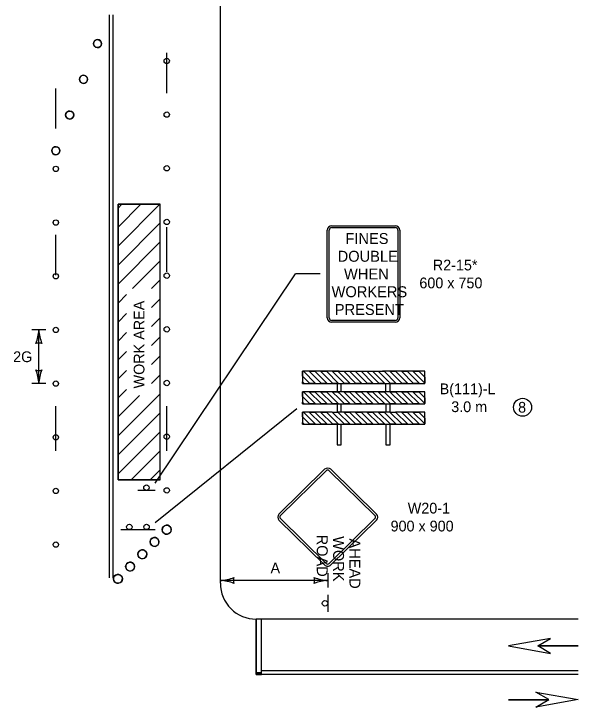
# Model space of a CAD drawing. Extents: x 49991.4 to 50021, y 49987.6 to 50011.4.
# Drawn here: x 50009.955 to 50013.109, y 49992.332 to 49996.207 of the extents above; entities that cross this region are included whole.
import ezdxf

# ---------------------------------------------------------------- set-up
doc = ezdxf.new("R2010")
doc.units = 0
for name, color, linetype in [('Level 1', 7, 'Continuous'), ('Level 2', 7, 'Continuous'), ('Level 3', 7, 'Continuous')]:
    doc.layers.add(name, color=color, linetype=linetype)

msp = doc.modelspace()

# ---------------------------------------------------------------- linework, layer by layer
at = {"layer": 'Level 1'}
for p, q in [((50011.109, 49995.0313), (50011.109, 49998.8719)), ((50010.489, 49995.4153), (50010.489, 49996.2021)), ((50010.509, 49995.4153), (50010.509, 49996.2021)), ((50010.8092, 49995.764), (50010.8092, 49995.988)), ((50010.1892, 49995.5651), (50010.1892, 49995.7891)), ((50010.489, 49995.3665), (50010.489, 49995.6141)), ((50010.509, 49995.3141), (50010.509, 49995.6141)), ((50010.489, 49995.0665), (50010.489, 49995.3665)), ((50010.509, 49995.0141), (50010.509, 49995.3141)), ((50010.5369, 49993.6029), (50010.5369, 49995.1428)), ((50010.5369, 49995.1428), (50010.7724, 49995.1428)), ((50010.5369, 49995.1207), (50010.559, 49995.1428)), ((50010.5369, 49995.0146), (50010.665, 49995.1428)), ((50010.5369, 49994.9086), (50010.7711, 49995.1428)), ((50010.7724, 49993.6029), (50010.7724, 49995.1428)), ((50010.489, 49994.7665), (50010.489, 49995.0665)), ((50010.5369, 49994.8025), (50010.7724, 49995.038)), ((50011.109, 49993.024), (50011.109, 49995.0313)), ((50010.509, 49994.7141), (50010.509, 49995.0141)), ((50010.8092, 49994.764), (50010.8092, 49995.014)), ((50011.7068, 49994.5081), (50011.7068, 49994.9975)), ((50011.7173, 49994.5081), (50011.7173, 49994.9975)), ((50011.7321, 49995.0228), (50012.0865, 49995.0228)), ((50011.7321, 49995.0123), (50012.0865, 49995.0123)), ((50011.9093, 49995.0228), (50011.9093, 49995.0228)), ((50012.1013, 49994.9975), (50012.1013, 49994.5081)), ((50012.1118, 49994.9975), (50012.1118, 49994.5081)), ((50010.1892, 49994.7461), (50010.1892, 49994.9711)), ((50010.5369, 49994.6964), (50010.7724, 49994.9319)), ((50010.6178, 49994.6712), (50010.7724, 49994.8259)), ((50010.489, 49994.4141), (50010.489, 49994.7665)), ((50010.7238, 49994.6712), (50010.7724, 49994.7198)), ((50010.509, 49994.4141), (50010.509, 49994.7141)), ((50010.5369, 49994.5904), (50010.5846, 49994.6381)), ((50010.7246, 49994.566), (50010.7724, 49994.6137)), ((50010.5369, 49994.4843), (50010.5846, 49994.5321)), ((50010.7246, 49994.4599), (50010.7724, 49994.5077)), ((50012.0865, 49994.4933), (50011.7321, 49994.4933)), ((50012.0865, 49994.4827), (50011.7321, 49994.4827)), ((50010.489, 49994.1141), (50010.489, 49994.4141)), ((50010.509, 49994.1141), (50010.509, 49994.4141)), ((50010.5369, 49994.3783), (50010.5846, 49994.426)), ((50010.7246, 49994.3539), (50010.7724, 49994.4016)), ((50010.5369, 49994.2722), (50010.5846, 49994.3199)), ((50010.7246, 49994.2478), (50010.7724, 49994.2956)), ((50010.5369, 49994.1661), (50010.5846, 49994.2139)), ((50010.7246, 49994.1417), (50010.7724, 49994.1895)), ((50011.6091, 49994.1407), (50011.5673, 49994.1824)), ((50011.6091, 49994.1407), (50011.5673, 49994.1824)), ((50011.6413, 49994.1407), (50011.5729, 49994.2091)), ((50011.5729, 49994.2091), (50011.6413, 49994.1407)), ((50011.6736, 49994.1407), (50011.6052, 49994.2091)), ((50011.6736, 49994.1407), (50011.6052, 49994.2091)), ((50011.7058, 49994.1407), (50011.6374, 49994.2091)), ((50011.6374, 49994.2091), (50011.7058, 49994.1407)), ((50011.738, 49994.1407), (50011.6696, 49994.2091)), ((50011.738, 49994.1407), (50011.6696, 49994.2091)), ((50011.7703, 49994.1407), (50011.7019, 49994.2091)), ((50011.7019, 49994.2091), (50011.7703, 49994.1407)), ((50011.8025, 49994.1407), (50011.7341, 49994.2091)), ((50011.8347, 49994.1407), (50011.7663, 49994.2091)), ((50011.7663, 49994.2091), (50011.8062, 49994.2091)), ((50011.7868, 49994.2091), (50012.0318, 49994.2091)), ((50011.8669, 49994.1407), (50011.7985, 49994.2091)), ((50011.8991, 49994.1407), (50011.8308, 49994.2091)), ((50011.9313, 49994.1407), (50011.863, 49994.2091)), ((50011.9636, 49994.1407), (50011.8952, 49994.2091)), ((50011.9958, 49994.1407), (50011.9274, 49994.2091)), ((50012.028, 49994.1407), (50011.9596, 49994.2091)), ((50012.0604, 49994.1407), (50011.992, 49994.2091)), ((50012.0461, 49994.2091), (50012.0148, 49994.2091)), ((50012.0926, 49994.1407), (50012.0242, 49994.2091)), ((50012.1249, 49994.1407), (50012.0565, 49994.2091)), ((50012.1249, 49994.1407), (50012.0565, 49994.2091)), ((50012.1571, 49994.1407), (50012.0887, 49994.2091)), ((50012.0887, 49994.2091), (50012.1571, 49994.1407)), ((50012.1894, 49994.1407), (50012.121, 49994.2091)), ((50012.1894, 49994.1407), (50012.121, 49994.2091)), ((50012.2216, 49994.1407), (50012.1532, 49994.2091)), ((50012.1532, 49994.2091), (50012.2216, 49994.1407)), ((50012.2513, 49994.1432), (50012.1854, 49994.2091)), ((50012.2513, 49994.1432), (50012.1854, 49994.2091)), ((50012.2513, 49994.1755), (50012.2177, 49994.2091)), ((50012.2177, 49994.2091), (50012.2513, 49994.1755)), ((50011.5768, 49994.1407), (50011.5673, 49994.1502)), ((50011.5673, 49994.1502), (50011.5768, 49994.1407)), ((50011.7839, 49994.0951), (50011.7839, 49994.1407)), ((50012.0347, 49994.0951), (50012.0347, 49994.1407)), ((50010.489, 49993.8665), (50010.489, 49994.1141)), ((50010.509, 49993.8141), (50010.509, 49994.1141)), ((50010.5369, 49994.0601), (50010.5846, 49994.1078)), ((50010.5369, 49993.8479), (50010.7724, 49994.0834)), ((50010.5369, 49993.954), (50010.6573, 49994.0744)), ((50011.6091, 49994.0267), (50011.5673, 49994.0685)), ((50011.6091, 49994.0267), (50011.5673, 49994.0685)), ((50011.6413, 49994.0267), (50011.5729, 49994.0951)), ((50011.5729, 49994.0951), (50011.6413, 49994.0267)), ((50011.6736, 49994.0267), (50011.6052, 49994.0951)), ((50011.6736, 49994.0267), (50011.6052, 49994.0951)), ((50011.7058, 49994.0267), (50011.6374, 49994.0951)), ((50011.6374, 49994.0951), (50011.7058, 49994.0267)), ((50011.738, 49994.0267), (50011.6696, 49994.0951)), ((50011.738, 49994.0267), (50011.6696, 49994.0951)), ((50011.7703, 49994.0267), (50011.7019, 49994.0951)), ((50011.7019, 49994.0951), (50011.7703, 49994.0267)), ((50011.7725, 49994.0568), (50011.7341, 49994.0951)), ((50011.7725, 49994.089), (50011.7663, 49994.0951)), ((50011.8347, 49994.0267), (50011.7725, 49994.089)), ((50011.867, 49994.0267), (50011.7986, 49994.0951)), ((50011.8992, 49994.0267), (50011.8308, 49994.0951)), ((50011.9315, 49994.0267), (50011.8631, 49994.0951)), ((50011.9637, 49994.0267), (50011.8953, 49994.0951)), ((50011.9959, 49994.0267), (50011.9275, 49994.0951)), ((50012.0282, 49994.0267), (50011.9598, 49994.0951)), ((50012.0604, 49994.0267), (50011.992, 49994.0951)), ((50012.0926, 49994.0267), (50012.0242, 49994.0951)), ((50012.1249, 49994.0267), (50012.0565, 49994.0951)), ((50012.1249, 49994.0267), (50012.0565, 49994.0951)), ((50012.1571, 49994.0267), (50012.0887, 49994.0951)), ((50012.0887, 49994.0951), (50012.1571, 49994.0267)), ((50012.1894, 49994.0267), (50012.121, 49994.0951)), ((50012.1894, 49994.0267), (50012.121, 49994.0951)), ((50012.2216, 49994.0267), (50012.1532, 49994.0951)), ((50012.1532, 49994.0951), (50012.2216, 49994.0267)), ((50012.2513, 49994.0293), (50012.1854, 49994.0951)), ((50012.2513, 49994.0293), (50012.1854, 49994.0951)), ((50012.2513, 49994.0615), (50012.2177, 49994.0951)), ((50012.2177, 49994.0951), (50012.2513, 49994.0615)), ((50011.5768, 49994.0267), (50011.5673, 49994.0363)), ((50011.5673, 49994.0363), (50011.5768, 49994.0267)), ((50011.8025, 49994.0267), (50011.7725, 49994.0568)), ((50010.1892, 49993.764), (50010.1892, 49994.014)), ((50010.8092, 49993.764), (50010.8092, 49994.014)), ((50010.5369, 49993.7419), (50010.7724, 49993.9774)), ((50011.6091, 49993.9128), (50011.5673, 49993.9545)), ((50011.6091, 49993.9128), (50011.5673, 49993.9545)), ((50011.6413, 49993.9128), (50011.5729, 49993.9812)), ((50011.5729, 49993.9812), (50011.6413, 49993.9128)), ((50011.6736, 49993.9128), (50011.6052, 49993.9812)), ((50011.6736, 49993.9128), (50011.6052, 49993.9812)), ((50011.7058, 49993.9128), (50011.6374, 49993.9812)), ((50011.6374, 49993.9812), (50011.7058, 49993.9128)), ((50011.738, 49993.9128), (50011.6696, 49993.9812)), ((50011.738, 49993.9128), (50011.6696, 49993.9812)), ((50011.7703, 49993.9128), (50011.7019, 49993.9812)), ((50011.7019, 49993.9812), (50011.7703, 49993.9128)), ((50011.8025, 49993.9128), (50011.7341, 49993.9812)), ((50011.8025, 49993.9128), (50011.7341, 49993.9812)), ((50011.8347, 49993.9128), (50011.7663, 49993.9812)), ((50011.7663, 49993.9812), (50011.8347, 49993.9128)), ((50011.867, 49993.9128), (50011.7986, 49993.9812)), ((50011.867, 49993.9128), (50011.7986, 49993.9812)), ((50011.8992, 49993.9128), (50011.8308, 49993.9812)), ((50011.8308, 49993.9812), (50011.8992, 49993.9128)), ((50011.9315, 49993.9128), (50011.8631, 49993.9812)), ((50011.9315, 49993.9128), (50011.8631, 49993.9812)), ((50011.9637, 49993.9128), (50011.8953, 49993.9812)), ((50011.8953, 49993.9812), (50011.9637, 49993.9128)), ((50011.9959, 49993.9128), (50011.9275, 49993.9812)), ((50011.9959, 49993.9128), (50011.9275, 49993.9812)), ((50012.0282, 49993.9128), (50011.9598, 49993.9812)), ((50011.9598, 49993.9812), (50012.0282, 49993.9128)), ((50012.0604, 49993.9128), (50011.992, 49993.9812)), ((50012.0604, 49993.9128), (50011.992, 49993.9812)), ((50012.0926, 49993.9128), (50012.0242, 49993.9812)), ((50012.0242, 49993.9812), (50012.0926, 49993.9128)), ((50012.1249, 49993.9128), (50012.0565, 49993.9812)), ((50012.1249, 49993.9128), (50012.0565, 49993.9812)), ((50012.1571, 49993.9128), (50012.0887, 49993.9812)), ((50012.0887, 49993.9812), (50012.1571, 49993.9128)), ((50012.1894, 49993.9128), (50012.121, 49993.9812)), ((50012.1894, 49993.9128), (50012.121, 49993.9812)), ((50012.2216, 49993.9128), (50012.1532, 49993.9812)), ((50012.1532, 49993.9812), (50012.2216, 49993.9128)), ((50012.2513, 49993.9153), (50012.1854, 49993.9812)), ((50012.2513, 49993.9153), (50012.1854, 49993.9812)), ((50012.2513, 49993.9476), (50012.2177, 49993.9812)), ((50012.2177, 49993.9812), (50012.2513, 49993.9476)), ((50011.5768, 49993.9128), (50011.5673, 49993.9223)), ((50011.5673, 49993.9223), (50011.5768, 49993.9128)), ((50010.489, 49993.5782), (50010.489, 49993.8665)), ((50010.5369, 49993.6358), (50010.7724, 49993.8713)), ((50010.509, 49993.5024), (50010.509, 49993.8141)), ((50010.61, 49993.6029), (50010.7724, 49993.7652)), ((50010.7161, 49993.6029), (50010.7724, 49993.6592)), ((50011.4366, 49993.4113), (50011.6919, 49993.6613)), ((50011.4448, 49993.4029), (50011.7001, 49993.653)), ((50011.7179, 49993.653), (50011.9731, 49993.4029)), ((50011.7261, 49993.6613), (50011.9813, 49993.4113)), ((50010.7724, 49993.6029), (50010.5369, 49993.6029)), ((50010.489, 49993.2782), (50010.489, 49993.5782)), ((50010.509, 49993.5153), (50010.509, 49993.5174)), ((50010.7441, 49993.5435), (50010.6481, 49993.5435)), ((50010.509, 49993.2782), (50010.509, 49993.5024)), ((50011.6919, 49993.127), (50011.4366, 49993.377)), ((50011.7001, 49993.1353), (50011.4448, 49993.3854)), ((50011.9731, 49993.3854), (50011.7179, 49993.1353)), ((50011.9813, 49993.377), (50011.7261, 49993.127)), ((50010.5521, 49993.3239), (50010.6481, 49993.3239)), ((50010.6481, 49993.3239), (50010.7441, 49993.3239)), ((50010.489, 49993.054), (50010.489, 49993.2782)), ((50010.509, 49993.054), (50010.509, 49993.2782)), ((50010.509, 49993.2153), (50010.509, 49993.2174)), ((50010.5463, 49993.024), (50010.5463, 49993.0261)), ((50011.709, 49992.96), (50011.709, 49992.864)), ((50013.109, 49992.824), (50011.309, 49992.824)), ((50011.309, 49992.5141), (50011.309, 49992.824)), ((50011.339, 49992.5141), (50011.339, 49992.824)), ((50013.109, 49992.6741), (50012.8831, 49992.6741)), ((50013.109, 49992.6737), (50012.8831, 49992.6737)), ((50011.339, 49992.5241), (50011.309, 49992.5241)), ((50013.109, 49992.5141), (50011.309, 49992.5141)), ((50013.109, 49992.5341), (50011.339, 49992.5341)), ((50012.7189, 49992.3741), (50012.9448, 49992.3741)), ((50012.7189, 49992.3737), (50012.9448, 49992.3737))]:
    msp.add_line(p, q, dxfattribs=at)
for points in [[(50010.7724, 49993.6029), (50010.7724, 49995.1428), (50010.5369, 49995.1428), (50010.5369, 49993.6029), (50010.7724, 49993.6029)], [(50011.7725, 49994.2091), (50011.5673, 49994.2091), (50011.5673, 49994.1407), (50011.7725, 49994.1407)], [(50011.5673, 49994.1824), (50011.5673, 49994.2091), (50011.5729, 49994.2091)], [(50011.6052, 49994.2091), (50011.6374, 49994.2091)], [(50011.6696, 49994.2091), (50011.7019, 49994.2091)], [(50011.8347, 49994.1407), (50011.8025, 49994.1407), (50011.7341, 49994.2091), (50011.7663, 49994.2091), (50011.8347, 49994.1407)], [(50011.7725, 49994.1407), (50012.2513, 49994.1407), (50012.2513, 49994.2091), (50012.0461, 49994.2091)], [(50011.7985, 49994.2091), (50011.8062, 49994.2091), (50011.8308, 49994.2091), (50011.8991, 49994.1407), (50011.8669, 49994.1407), (50011.7985, 49994.2091)], [(50011.863, 49994.2091), (50011.8952, 49994.2091), (50011.9636, 49994.1407), (50011.9313, 49994.1407), (50011.863, 49994.2091)], [(50011.9274, 49994.2091), (50011.9596, 49994.2091), (50012.028, 49994.1407), (50011.9958, 49994.1407), (50011.9274, 49994.2091)], [(50011.992, 49994.2091), (50012.0148, 49994.2091), (50012.0242, 49994.2091), (50012.0926, 49994.1407), (50012.0604, 49994.1407), (50011.992, 49994.2091)], [(50012.0565, 49994.2091), (50012.0887, 49994.2091)], [(50012.121, 49994.2091), (50012.1532, 49994.2091)], [(50012.1854, 49994.2091), (50012.2177, 49994.2091)], [(50012.2513, 49994.1755), (50012.2513, 49994.1432)], [(50011.5768, 49994.1407), (50011.5673, 49994.1407), (50011.5673, 49994.1502)], [(50011.6413, 49994.1407), (50011.6091, 49994.1407)], [(50011.7058, 49994.1407), (50011.6736, 49994.1407)], [(50011.7703, 49994.1407), (50011.738, 49994.1407)], [(50011.7611, 49994.1407), (50011.7611, 49994.0951)], [(50012.0575, 49994.0951), (50012.0575, 49994.1407)], [(50012.1571, 49994.1407), (50012.1249, 49994.1407)], [(50012.2216, 49994.1407), (50012.1894, 49994.1407)], [(50011.7725, 49994.0951), (50011.5673, 49994.0951), (50011.5673, 49994.0267), (50012.2513, 49994.0267), (50012.2513, 49994.0951), (50011.7725, 49994.0951)], [(50011.5673, 49994.0685), (50011.5673, 49994.0951), (50011.5729, 49994.0951)], [(50011.6052, 49994.0951), (50011.6374, 49994.0951)], [(50011.6696, 49994.0951), (50011.7019, 49994.0951)], [(50011.8347, 49994.0267), (50011.8025, 49994.0267), (50011.7725, 49994.0568), (50011.7341, 49994.0951), (50011.7611, 49994.0951), (50011.7663, 49994.0951), (50011.7725, 49994.089), (50011.8347, 49994.0267)], [(50011.7986, 49994.0951), (50011.8308, 49994.0951), (50011.8992, 49994.0267), (50011.867, 49994.0267), (50011.7986, 49994.0951)], [(50011.8631, 49994.0951), (50011.8953, 49994.0951), (50011.9637, 49994.0267), (50011.9315, 49994.0267), (50011.8631, 49994.0951)], [(50011.9275, 49994.0951), (50011.9598, 49994.0951), (50012.0282, 49994.0267), (50011.9959, 49994.0267), (50011.9275, 49994.0951)], [(50011.992, 49994.0951), (50012.0242, 49994.0951), (50012.0926, 49994.0267), (50012.0604, 49994.0267), (50011.992, 49994.0951)], [(50012.0565, 49994.0951), (50012.0887, 49994.0951)], [(50012.121, 49994.0951), (50012.1532, 49994.0951)], [(50012.1854, 49994.0951), (50012.2177, 49994.0951)], [(50012.2513, 49994.0615), (50012.2513, 49994.0293)], [(50011.5768, 49994.0267), (50011.5673, 49994.0267), (50011.5673, 49994.0363)], [(50011.6413, 49994.0267), (50011.6091, 49994.0267)], [(50011.7058, 49994.0267), (50011.6736, 49994.0267)], [(50011.7703, 49994.0267), (50011.738, 49994.0267)], [(50011.7611, 49994.0267), (50011.7611, 49993.9812)], [(50011.7839, 49993.9812), (50011.7839, 49994.0267)], [(50012.0347, 49994.0267), (50012.0347, 49993.9812)], [(50012.0575, 49993.9812), (50012.0575, 49994.0267)], [(50012.1571, 49994.0267), (50012.1249, 49994.0267)], [(50012.2216, 49994.0267), (50012.1894, 49994.0267)], [(50011.5673, 49993.9545), (50011.5673, 49993.9812), (50011.5729, 49993.9812)], [(50011.7341, 49993.9812), (50011.5673, 49993.9812), (50011.5673, 49993.9128), (50012.2513, 49993.9128), (50012.2513, 49993.9812), (50012.0887, 49993.9812)], [(50011.6052, 49993.9812), (50011.6374, 49993.9812)], [(50011.6696, 49993.9812), (50011.7019, 49993.9812)], [(50011.7341, 49993.9812), (50011.7663, 49993.9812)], [(50012.0565, 49993.9812), (50011.7663, 49993.9812)], [(50011.7986, 49993.9812), (50011.8308, 49993.9812)], [(50011.8631, 49993.9812), (50011.8953, 49993.9812)], [(50011.9275, 49993.9812), (50011.9598, 49993.9812)], [(50011.992, 49993.9812), (50012.0242, 49993.9812)], [(50012.0565, 49993.9812), (50012.0887, 49993.9812)], [(50012.121, 49993.9812), (50012.1532, 49993.9812)], [(50012.1854, 49993.9812), (50012.2177, 49993.9812)], [(50012.2513, 49993.9476), (50012.2513, 49993.9153)], [(50011.5768, 49993.9128), (50011.5673, 49993.9128), (50011.5673, 49993.9223)], [(50011.6413, 49993.9128), (50011.6091, 49993.9128)], [(50011.7058, 49993.9128), (50011.6736, 49993.9128)], [(50011.7703, 49993.9128), (50011.738, 49993.9128)], [(50011.7611, 49993.9127), (50011.7611, 49993.7987), (50011.7839, 49993.7987), (50011.7839, 49993.9127)], [(50011.8347, 49993.9128), (50011.8025, 49993.9128)], [(50011.8992, 49993.9128), (50011.867, 49993.9128)], [(50011.9637, 49993.9128), (50011.9315, 49993.9128)], [(50012.0282, 49993.9128), (50011.9959, 49993.9128)], [(50012.0347, 49993.9127), (50012.0347, 49993.7987), (50012.0575, 49993.7987), (50012.0575, 49993.9127)], [(50012.0926, 49993.9128), (50012.0604, 49993.9128)], [(50012.1571, 49993.9128), (50012.1249, 49993.9128)], [(50012.2216, 49993.9128), (50012.1894, 49993.9128)], [(50011.339, 49992.824), (50011.309, 49992.824), (50011.309, 49992.5241), (50011.339, 49992.5241), (50011.339, 49992.824)], [(50011.309, 49992.5141), (50011.339, 49992.5141), (50011.339, 49992.5241), (50011.309, 49992.5241), (50011.309, 49992.5141)]]:
    msp.add_lwpolyline(points, dxfattribs=at)
for points in [[(50012.9554, 49992.7157), (50012.7189, 49992.6741), (50012.9554, 49992.6321), (50012.8832, 49992.6741)], [(50012.8725, 49992.4157), (50013.109, 49992.3741), (50012.8725, 49992.3321), (50012.9447, 49992.3741)]]:
    msp.add_lwpolyline(points, close=True, dxfattribs=at)
for centre, radius in [((50010.4216, 49996.0405), 0.0225), ((50010.8091, 49995.9435), 0.015), ((50010.3441, 49995.8408), 0.0225), ((50010.2666, 49995.6411), 0.0225), ((50010.8091, 49995.6435), 0.015), ((50010.1892, 49995.4415), 0.0225), ((50010.1892, 49995.3403), 0.015), ((50010.8091, 49995.3435), 0.015), ((50010.1892, 49995.0403), 0.015), ((50010.8091, 49995.0435), 0.015), ((50010.8091, 49994.7435), 0.015), ((50010.1892, 49994.7403), 0.015), ((50010.1892, 49994.4403), 0.015), ((50010.8091, 49994.4435), 0.015), ((50010.1892, 49994.1403), 0.015), ((50010.8091, 49994.1435), 0.015), ((50010.1892, 49993.8403), 0.015), ((50010.8091, 49993.8435), 0.015), ((50010.696, 49993.5586), 0.0152), ((50010.8091, 49993.5435), 0.015), ((50010.1892, 49993.5403), 0.015), ((50010.6001, 49993.3391), 0.0152), ((50010.6961, 49993.3391), 0.0152), ((50010.8091, 49993.3239), 0.025), ((50010.1892, 49993.2403), 0.015), ((50010.7409, 49993.2552), 0.025), ((50010.6727, 49993.1865), 0.025), ((50010.6045, 49993.1177), 0.025), ((50010.5363, 49993.049), 0.025), ((50010.5363, 49993.049), 0.025), ((50011.6939, 49992.9119), 0.0152)]:
    msp.add_circle(centre, radius, dxfattribs=at)
for centre, radius, start, end in [((50010.4216, 49996.0405), 0.0225, 356.6361, 176.6361), ((50010.4216, 49996.0405), 0.0225, 176.6361, 356.6361), ((50010.3441, 49995.8408), 0.0225, 356.6361, 176.6361), ((50010.3441, 49995.8408), 0.0225, 176.6361, 356.6361), ((50010.2666, 49995.6411), 0.0225, 356.6361, 176.6361), ((50010.2666, 49995.6411), 0.0225, 176.6361, 356.6361), ((50010.1892, 49995.4415), 0.0225, 356.6361, 176.6361), ((50010.1892, 49995.4415), 0.0225, 176.6361, 356.6361), ((50011.7321, 49994.9975), 0.0253, 90, 180), ((50011.7321, 49994.9975), 0.0148, 90, 180), ((50012.0865, 49994.9975), 0.0253, 0, 90), ((50012.0865, 49994.9975), 0.0148, 0, 90), ((50011.7321, 49994.5081), 0.0253, 180, 270), ((50011.7321, 49994.5081), 0.0148, 180, 270), ((50012.0865, 49994.5081), 0.0148, 270, 360), ((50012.0865, 49994.5081), 0.0253, 270, 360), ((50010.8091, 49993.3239), 0.025, 99.0657, 279.0657), ((50010.8091, 49993.3239), 0.025, 279.0657, 99.0657), ((50010.7409, 49993.2552), 0.025, 99.0657, 279.0657), ((50010.7409, 49993.2552), 0.025, 279.0657, 99.0657), ((50010.6727, 49993.1865), 0.025, 99.0657, 279.0657), ((50010.6727, 49993.1865), 0.025, 279.0657, 99.0657), ((50010.6045, 49993.1177), 0.025, 99.0657, 279.0657), ((50010.6045, 49993.1177), 0.025, 279.0657, 99.0657), ((50010.5363, 49993.049), 0.025, 99.0657, 279.0657), ((50010.5363, 49993.049), 0.025, 99.0657, 279.0657), ((50010.5363, 49993.049), 0.025, 279.0657, 99.0657), ((50010.5363, 49993.049), 0.025, 279.0657, 99.0657), ((50011.309, 49993.024), 0.2, 180, 270.0006)]:
    msp.add_arc(centre, radius, start, end, dxfattribs=at)
for centre, major_axis, ratio, start_param, end_param in [((50011.709, 49993.6443), (-0.0243, 0), 0.98963, 3.926991, 5.497787), ((50011.709, 49993.6443), (-0.0126, 0), 0.98, 3.926991, 5.497787), ((50011.4538, 49993.3941), (-0.0243, 0), 0.98963, 5.497787, 7.068583), ((50011.4538, 49993.3941), (-0.0126, 0), 0.98, 5.497787, 7.068583), ((50011.9643, 49993.3941), (0.0126, 0), 0.98, 5.497795, 7.068583), ((50011.9643, 49993.3941), (0.0243, 0), 0.98963, 5.497795, 7.068583), ((50011.709, 49993.144), (-0.0126, 0), 0.98, 0.785394, 2.356194), ((50011.709, 49993.144), (-0.0243, 0), 0.98963, 0.785394, 2.356194)]:
    msp.add_ellipse(centre, major_axis=major_axis, ratio=ratio, start_param=start_param, end_param=end_param, dxfattribs=at)
at = {"layer": 'Level 2'}
msp.add_circle((50012.7984, 49994.0078), 0.0501, dxfattribs=at)
at = {"layer": 'Level 3'}
for p, q in [((50010.7441, 49993.5835), (50011.5284, 49994.7528)), ((50011.6668, 49994.7528), (50011.5284, 49994.7528)), ((50010.1342, 49994.4403), (50010.0542, 49994.4403)), ((50010.0942, 49994.1403), (50010.0942, 49994.4403)), ((50010.1342, 49994.1403), (50010.0542, 49994.1403)), ((50010.7441, 49993.3639), (50011.5362, 49994.0017)), ((50011.709, 49993.08), (50011.709, 49993)), ((50011.709, 49993.04), (50011.109, 49993.04))]:
    msp.add_line(p, q, dxfattribs=at)
for centre, radius, start, end in [((50009.872, 49994.4495), 0.2223, 337.456, 357.6395), ((50010.3269, 49994.4518), 0.233, 182.8273, 202.0772), ((50010.0942, 49994.3121), 0.0548, 72.1388, 107.8612), ((50010.0942, 49994.2685), 0.0548, 252.1388, 287.8612), ((50009.8614, 49994.1288), 0.233, 2.8273, 22.0772), ((50010.3163, 49994.1311), 0.2223, 157.456, 177.6395), ((50011.0975, 49993.2727), 0.233, 272.8273, 292.0772), ((50011.2372, 49993.04), 0.0548, 162.1388, 197.8612), ((50011.7182, 49993.2621), 0.2223, 247.456, 267.6395), ((50011.5808, 49993.04), 0.0548, 342.1388, 17.8612), ((50011.0999, 49992.8179), 0.2223, 67.456, 87.6395), ((50011.7205, 49992.8073), 0.233, 92.8273, 112.0772)]:
    msp.add_arc(centre, radius, start, end, dxfattribs=at)

# ---------------------------------------------------------------- texts
at = {"layer": 'Level 1'}
for s, p in [('FINES', (50011.8081, 49994.9205)), ('DOUBLE', (50011.7647, 49994.8213)), ('WHEN', (50011.8001, 49994.7222)), ('WORKERS', (50011.7307, 49994.623)), ('PRESENT', (50011.7488, 49994.5239))]:
    msp.add_text(s, height=0.06118, dxfattribs=at).set_placement(p)
for s, p in [('ROAD', (50011.6482, 49993.2959)), ('WORK', (50011.7394, 49993.2874)), ('AHEAD', (50011.8307, 49993.2744))]:
    msp.add_text(s, height=0.06086, rotation=270, dxfattribs=at).set_placement(p)
at = {"layer": 'Level 2'}
for s, p in [('R2-15*', (50012.2966, 49994.7728)), ('600 x 750', (50012.2214, 49994.6728)), ('2G', (50009.9505, 49994.2603)), ('B(111)-L', (50012.335, 49994.0809)), ('3.0 m', (50012.3996, 49993.9809)), ('8', (50012.7735, 49993.9778))]:
    msp.add_text(s, height=0.06, dxfattribs=at).set_placement(p)
for s, rotation, p in [('WORK AREA', 90, (50010.6846, 49994.1132)), ('W20-1', 360, (50012.1564, 49993.4141)), ('900 x 900', 360, (50012.0605, 49993.3141)), ('A', 360, (50011.3894, 49993.08))]:
    msp.add_text(s, height=0.06, rotation=rotation, dxfattribs=at).set_placement(p)

doc.saveas('drawing.dxf')
